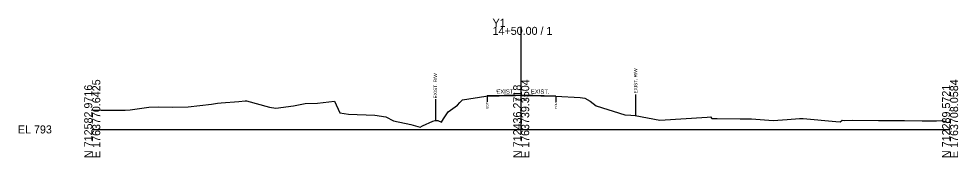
# Model space of a CAD drawing. Extents: x -26 to 1303, y -10 to 9524.
# Drawn here: x -25.7 to 302.8, y 4490.3 to 4538.6 of the extents above; entities that cross this region are included whole.
import ezdxf

# ---------------------------------------------------------------- set-up
doc = ezdxf.new("R2010")
doc.units = 0
for name, color, linetype in [('Default', 7, 'Continuous'), ('Exist Cross Section Cell', 7, 'Continuous'), ('Exist XS Center Line Elevation Label', 7, 'Continuous'), ('Exist XS Ground Line', 7, 'Continuous'), ('Old_Level_10', 7, 'Continuous'), ('Prop CMT Pvmt Surface Overlay', 7, 'Continuous'), ('Prop XS SE Text', 7, 'Continuous')]:
    doc.layers.add(name, color=color, linetype=linetype)

msp = doc.modelspace()

# ---------------------------------------------------------------- linework, layer by layer
at = {"layer": 'Exist Cross Section Cell'}
for p, q in [((150, 4500), (150, 4535.81)), ((0, 4500), (150, 4500)), ((150, 4500), (300, 4500))]:
    msp.add_line(p, q, dxfattribs=at)
at = {"layer": 'Exist XS Ground Line'}
msp.add_lwpolyline([(0, 4506.8), (3.08, 4506.71), (11.47, 4506.76), (13.26, 4506.86), (19.84, 4507.81), (23.32, 4507.92), (28.23, 4507.73), (33.55, 4507.94), (41.75, 4508.87), (43.77, 4509.18), (45.09, 4509.28), (51.24, 4509.78), (53.52, 4509.95), (54, 4509.95), (61.94, 4507.81), (64.23, 4507.39), (70.37, 4508.27), (74.45, 4509.07), (78.8, 4509.21), (84.68, 4509.91), (86.6, 4505.78), (89.67, 4505.36), (98.87, 4505.03), (102.63, 4504.34), (105.39, 4502.98), (111.44, 4501.7), (114.67, 4500.8), (115.47, 4501.28), (119.12, 4502.87), (119.92, 4503.12), (120.8, 4503.12), (122.1, 4502.54), (122.88, 4503.7), (124.42, 4506.09), (127.78, 4508.47), (128.58, 4509.42), (129.49, 4510.35), (137.63, 4511.58), (138.14, 4511.68), (139.38, 4511.71), (139.75, 4511.72), (140.14, 4511.73), (141.75, 4511.76), (142.35, 4511.77), (144.2, 4511.84), (144.91, 4511.85), (146, 4511.86), (147.47, 4511.86), (147.99, 4511.88), (149.55, 4511.93), (149.99, 4511.94), (150.44, 4511.93), (151.01, 4511.91), (151.45, 4511.89), (152.88, 4511.88), (155.13, 4511.84), (156.84, 4511.77), (157.98, 4511.72), (159.74, 4511.69), (160.12, 4511.67), (162.17, 4511.6), (170.61, 4511.16), (172.29, 4510.96), (174.13, 4509.84), (176.23, 4508.21), (186.27, 4505.09), (188.31, 4504.99), (189.82, 4504.87), (198.54, 4503.2), (215.08, 4504.22), (216.18, 4504.35), (216.7, 4503.84), (218.26, 4503.86), (218.58, 4503.86), (226.59, 4503.74), (230.51, 4503.69), (238.07, 4503.17), (243.01, 4503.49), (247.37, 4503.83), (248.56, 4503.82), (260.04, 4502.71), (261.6, 4502.59), (262.12, 4503.07), (262.24, 4503.21), (263.15, 4503.14), (265.92, 4503.18), (274.96, 4503.09), (284, 4503.13), (290.18, 4503.01), (295.29, 4502.98), (297, 4503.09), (297.48, 4502.96), (298.21, 4502.74), (299.11, 4502.47), (300, 4502.48)], dxfattribs=at)
at = {"layer": 'Old_Level_10'}
for p, q in [((138.14, 4511.68), (138.14, 4509.63)), ((162.17, 4511.6), (162.17, 4509.55)), ((190, 4512.23), (190, 4504.83)), ((120, 4510.52), (120, 4503.12))]:
    msp.add_line(p, q, dxfattribs=at)
at = {"layer": 'Prop CMT Pvmt Surface Overlay'}
for p, q in [((138.13, 4511.8), (150, 4512.06)), ((138.14, 4511.68), (150, 4511.94)), ((150, 4512.06), (162.17, 4511.73)), ((150, 4511.94), (162.17, 4511.6))]:
    msp.add_line(p, q, dxfattribs=at)

# ---------------------------------------------------------------- texts
at = {"layer": 'Default'}
msp.add_text('-', height=0.0001, dxfattribs=at).set_placement((0, 4500))
at = {"layer": 'Exist Cross Section Cell'}
for s, p in [('Y1', (140, 4535.81)), ('14+50.00 / 1', (140, 4533.01)), ('EL 793', (-26, 4498.6))]:
    msp.add_text(s, height=2.8, dxfattribs=at).set_placement(p)
for s, p in [('E 1763770.6425', (2.8, 4490)), ('E 1763739.3504', (152.8, 4490)), ('E 1763708.0584', (302.8, 4490)), ('N 712582.9716', (0, 4490)), ('N 712436.2718', (150, 4490)), ('N 712289.5721', (300, 4490))]:
    msp.add_text(s, height=2.8, rotation=90, dxfattribs=at).set_placement(p)
at = {"layer": 'Exist XS Center Line Elevation Label'}
msp.add_text('804.94', height=1, dxfattribs=at).set_placement((147.86, 4509.94))
at = {"layer": 'Old_Level_10'}
for s, height, p in [('EXIST. R/W', 1.181, (190.59, 4512.53)), ('EXIST. R/W', 1.181, (120.59, 4510.82)), ('EOP', 0.787, (138.53, 4507.23)), ('EOP', 0.787, (162.56, 4507.15))]:
    msp.add_text(s, height=height, rotation=90, dxfattribs=at).set_placement(p)
at = {"layer": 'Prop XS SE Text'}
for rotation, p in [(1.1458, (141.33, 4512.42)), (358.8542, (153.37, 4512.52))]:
    msp.add_text('EXIST.', height=1.5, rotation=rotation, dxfattribs=at).set_placement(p)

doc.saveas('drawing.dxf')
